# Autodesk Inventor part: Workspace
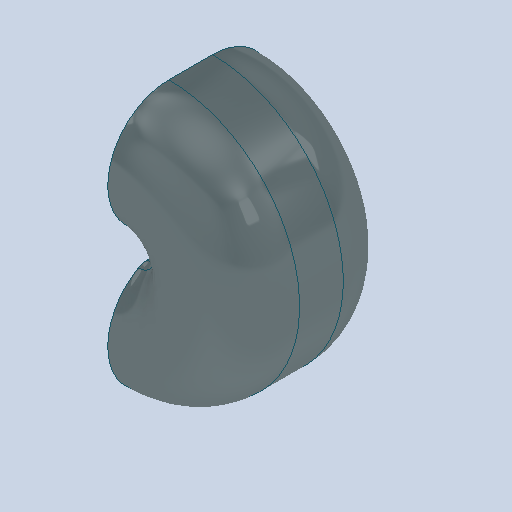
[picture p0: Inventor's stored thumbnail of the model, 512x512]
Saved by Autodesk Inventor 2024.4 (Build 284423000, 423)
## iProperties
Created: 2025-07
Part Number: Workspace
Material: Generic
Document SubType Name: Modeling
Designer: AdminForWorker
Density: 1 g/cm^3
Appearance: Default
Title: Workspace v3
Author: AdminForWorker
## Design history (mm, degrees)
feature "Body1"
body "Solid1"
